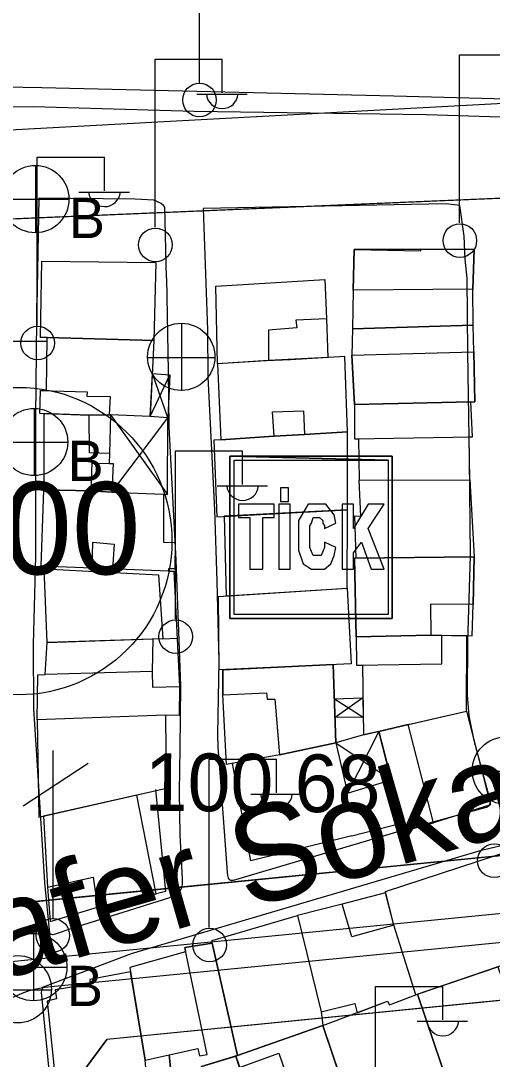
# Model space of a CAD drawing. Extents: x 417997 to 421451, y 4451742 to 4455216.
# Drawn here: x 419193.6 to 419242.7, y 4453532.7 to 4453640.7 of the extents above; entities that cross this region are included whole.
import ezdxf

# ---------------------------------------------------------------- set-up
doc = ezdxf.new("R2010")
doc.units = 0
for name, color, linetype in [('ADAKENARI', 7, 'Continuous'), ('B_Kapi', 7, 'Continuous'), ('B_Mesken', 7, 'Continuous'), ('B_Sundurma', 7, 'Continuous'), ('B_Teras', 7, 'Continuous'), ('Default', 7, 'Continuous'), ('KALDIRIM', 7, 'Continuous'), ('LJ_SEMBOL', 7, 'Continuous'), ('PL_AYA_PARK_DINLENME', 7, 'Continuous'), ('PL_TİCK', 7, 'Continuous'), ('S_Cad_Sok_Lambasi', 7, 'Continuous'), ('S_Cami_Mescid', 7, 'Continuous'), ('S_Elektrik_Diregi', 7, 'Continuous'), ('S_Rogar_Kapagi', 7, 'Continuous'), ('S_Rogar_Kapagi_Buski', 7, 'Continuous'), ('S_Telefon_Diregi', 7, 'Continuous'), ('Sinir_Duvar_tek_tarafa_ait', 7, 'Continuous'), ('Sinir_Tel_bir_taraf', 7, 'Continuous'), ('SM_TAKS', 7, 'Continuous'), ('TR_PARKALANI', 7, 'Continuous'), ('TR_TİCK', 7, 'Continuous'), ('Y_Cadde_Yol', 7, 'Continuous'), ('Y_Kot_Noktasi', 7, 'Continuous'), ('Yol_Sose', 7, 'Continuous')]:
    doc.layers.add(name, color=color, linetype=linetype)

# ---------------------------------------------------------------- blocks, each defined once
blk = doc.blocks.new('POINT_DISPLAY')
at = {"layer": 'Default'}
blk.add_line((0, 0), (0, 0), dxfattribs=at)

msp = doc.modelspace()

# ---------------------------------------------------------------- linework, layer by layer
at = {"layer": 'ADAKENARI'}
for p, q in [((419184.84, 4453619.74), (419327.19, 4453625.77)), ((419184.84, 4453619.74), (419327.19, 4453625.77)), ((419336.29, 4453563), (419170.94, 4453546.68)), ((419336.29, 4453563), (419170.94, 4453546.68)), ((419398.25, 4453554.05), (419202.53, 4453534.72)), ((419398.25, 4453554.05), (419202.53, 4453534.72)), ((419194.6, 4453523.95), (419202.53, 4453534.72)), ((419194.6, 4453523.95), (419202.53, 4453534.72))]:
    msp.add_line(p, q, dxfattribs=at)
at = {"layer": 'B_Kapi'}
msp.add_lwpolyline([(419228.07, 4453555.9), (419233.32, 4453557.24)], dxfattribs=at)
at = {"layer": 'B_Mesken'}
for points in [[(419240.67, 4453609.03), (419240.64, 4453612.77), (419240.78, 4453616.91), (419228.3, 4453616.91), (419228.2, 4453612.66), (419228.12, 4453608.66)], [(419196.33, 4453607.73), (419195.63, 4453607.73), (419195.77, 4453615.68), (419207.66, 4453615.53), (419207.45, 4453607.44)], [(419225.43, 4453609.7), (419225.56, 4453605.67), (419219.39, 4453605.34), (419214.05, 4453605.02), (419213.9, 4453613.1), (419225.25, 4453613.77)], [(419228.12, 4453608.66), (419228.07, 4453605.91), (419228.33, 4453600.78), (419240.44, 4453601.04), (419240.87, 4453601.05), (419240.75, 4453606.24), (419240.67, 4453609.03)], [(419207.07, 4453599.52), (419202.92, 4453599.7), (419202.78, 4453599.7), (419200.7, 4453599.65), (419195.58, 4453599.85), (419195.64, 4453602.24), (419196.27, 4453602.22), (419196.33, 4453607.73), (419207.45, 4453607.44)], [(419221.65, 4453605.43), (419219.12, 4453605.33), (419214.05, 4453605.02), (419214.42, 4453597.1), (419219.97, 4453597.48), (419223.13, 4453597.64), (419227.6, 4453597.92), (419227.31, 4453605.78)], [(419240.35, 4453592.93), (419240.28, 4453597.41), (419240.63, 4453597.42), (419240.44, 4453601.04), (419228.33, 4453600.78), (419228.33, 4453597.2), (419228.73, 4453597.2), (419228.83, 4453592.89)], [(419196.03, 4453591.9), (419196, 4453599.84), (419200.7, 4453599.65), (419202.78, 4453599.7), (419202.92, 4453599.7), (419202.82, 4453595.69), (419202.79, 4453594.63), (419203.21, 4453594.62), (419203.05, 4453591.65), (419200.92, 4453591.78), (419195.98, 4453591.9)], [(419214.42, 4453597.1), (419213.69, 4453597.06), (419213.98, 4453589.09), (419227.6, 4453589.82), (419227.6, 4453597.92), (419223.13, 4453597.64), (419219.97, 4453597.48)], [(419228.5, 4453584.8), (419228.37, 4453589.2), (419228.99, 4453589.14), (419228.83, 4453592.89), (419240.35, 4453592.93), (419240.8, 4453584.91)], [(419195.72, 4453583.94), (419195.98, 4453591.9), (419200.92, 4453591.78), (419203.05, 4453591.65), (419208.44, 4453591.44), (419208.44, 4453586.45), (419209.66, 4453586.42), (419209.61, 4453583.68), (419208.95, 4453583.68), (419208.95, 4453583.43)], [(419214.76, 4453589.14), (419214.97, 4453580.85), (419227.55, 4453581.66), (419227.6, 4453589.82)], [(419240.59, 4453576.69), (419240.7, 4453579.98), (419240.8, 4453584.91), (419228.34, 4453584.8), (419228.51, 4453576.61), (419236.28, 4453576.76)], [(419196.33, 4453576), (419196, 4453583.66), (419207.93, 4453583.04), (419208.38, 4453576.41)], [(419214.17, 4453580.79), (419227.55, 4453581.66), (419227.97, 4453573.8), (419214.24, 4453573.16)], [(419229.15, 4453573.66), (419229.28, 4453566.4), (419239.99, 4453568.88), (419240.02, 4453576.7), (419237.41, 4453576.74), (419236.28, 4453576.76), (419228.51, 4453576.61), (419228.54, 4453573.65)], [(419196.12, 4453572.67), (419196.33, 4453576), (419207.33, 4453576.38), (419207.25, 4453573.01), (419207.29, 4453571.38), (419210.12, 4453571.43), (419210.07, 4453568.42), (419208.67, 4453568.45), (419195.28, 4453567.97), (419195.37, 4453572.64)], [(419215.01, 4453563.31), (419214.63, 4453570.58), (419214.63, 4453573.18), (419226.12, 4453573.72), (419226.4, 4453565.58), (419220.51, 4453564.31)], [(419195.28, 4453567.97), (419195.47, 4453557.83), (419208.77, 4453560.84), (419208.67, 4453568.45)], [(419239.99, 4453568.88), (419242.49, 4453559.12), (419236.56, 4453557.25), (419233.53, 4453556.43), (419230.87, 4453566.76), (419233.93, 4453567.47)], [(419201.56, 4453548.47), (419207.69, 4453549.85), (419205.66, 4453560.14), (419195.94, 4453557.94), (419196.35, 4453550.54), (419196.64, 4453546.99)], [(419232.41, 4453546.61), (419231.55, 4453550.09), (419248.85, 4453555.75), (419249.06, 4453555.45), (419251.81, 4453545.22), (419248.63, 4453544.02), (419244.69, 4453542.75), (419243.26, 4453542.28), (419234.71, 4453539.34)], [(419231.57, 4453549.98), (419227.04, 4453548.8), (419222.4, 4453547.6), (419224.86, 4453537.58), (419228.36, 4453538.47), (419228.6, 4453537.5), (419231.78, 4453538.69), (419231.97, 4453538.31), (419234.71, 4453539.34), (419232.41, 4453546.61)], [(419213.5, 4453544.74), (419213.5, 4453545.01), (419222.4, 4453547.6), (419224.86, 4453537.58), (419225.04, 4453536.15), (419216.14, 4453533.04)], [(419204.93, 4453542.21), (419206.54, 4453532.55), (419209.04, 4453533.13), (419209.29, 4453530.71), (419212.47, 4453531.55), (419212.39, 4453531.9), (419216.14, 4453533.04), (419213.5, 4453544.74), (419210.65, 4453544.28), (419210.74, 4453543.84)], [(419238.22, 4453529.56), (419234.89, 4453539.41), (419243.26, 4453542.28), (419246.54, 4453532.66)], [(419205.01, 4453541.74), (419200.78, 4453540.94), (419200.8, 4453540.47), (419197.16, 4453539.86), (419197.29, 4453538.93), (419196.34, 4453538.7), (419197.57, 4453526.69), (419206.79, 4453529.84), (419206.54, 4453532.55)], [(419225.04, 4453536.15), (419231.78, 4453538.69), (419231.97, 4453538.31), (419234.89, 4453539.41), (419238.22, 4453529.56), (419238.46, 4453528.88), (419228.62, 4453525.55)], [(419228.5, 4453525.91), (419223.06, 4453524.01), (419223.03, 4453523.87), (419219.5, 4453522.6), (419218.29, 4453526.3), (419216.37, 4453531.8), (419215.96, 4453532.98), (419216.14, 4453533.04), (419225.04, 4453536.15)], [(419219.5, 4453522.6), (419209.49, 4453519.33), (419206.79, 4453529.84), (419209.29, 4453530.71), (419212.47, 4453531.55), (419212.39, 4453531.9), (419215.96, 4453532.98), (419216.87, 4453530.39), (419218.29, 4453526.3)]]:
    msp.add_lwpolyline(points, close=True, dxfattribs=at)
at = {"layer": 'B_Sundurma'}
for p, q in [((419207.07, 4453599.52), (419209.11, 4453603.85)), ((419208.91, 4453599.38), (419207.28, 4453604)), ((419202.92, 4453599.7), (419208.87, 4453591.41)), ((419203.05, 4453591.65), (419208.91, 4453599.38)), ((419226.24, 4453570.16), (419229.25, 4453568.26)), ((419229.21, 4453570.24), (419226.31, 4453568.22)), ((419230.87, 4453566.76), (419227.6, 4453560.35)), ((419226.4, 4453565.58), (419232.16, 4453561.74))]:
    msp.add_line(p, q, dxfattribs=at)
for points in [[(419208.91, 4453599.38), (419207.07, 4453599.52), (419207.28, 4453604), (419209.11, 4453603.85)], [(419207.07, 4453599.52), (419202.92, 4453599.7), (419202.82, 4453595.69), (419202.79, 4453594.63), (419202.79, 4453594.63), (419203.21, 4453594.62), (419203.05, 4453591.65), (419208.44, 4453591.44), (419208.87, 4453591.41), (419208.91, 4453599.38)], [(419226.24, 4453570.16), (419229.21, 4453570.24), (419229.25, 4453568.26), (419226.31, 4453568.22)], [(419230.87, 4453566.76), (419229.28, 4453566.4), (419226.4, 4453565.58), (419227.6, 4453560.35), (419232.16, 4453561.74)]]:
    msp.add_lwpolyline(points, close=True, dxfattribs=at)
at = {"layer": 'B_Teras'}
for points in [[(419228.2, 4453612.66), (419228.3, 4453616.91), (419235.22, 4453616.77), (419235.22, 4453616.77), (419235.22, 4453616.96), (419240.22, 4453616.94), (419240.78, 4453616.91), (419240.64, 4453612.77)], [(419214.05, 4453605.02), (419213.9, 4453613.1), (419225.25, 4453613.77), (419225.43, 4453609.7), (419222.23, 4453609.54), (419222.33, 4453608.75), (419219.37, 4453608.5), (419219.39, 4453605.34)], [(419228.07, 4453605.91), (419240.75, 4453606.24), (419240.87, 4453601.05), (419228.33, 4453600.78)], [(419202.78, 4453599.7), (419200.7, 4453599.65), (419195.58, 4453599.85), (419195.64, 4453602.24), (419200.49, 4453602.1), (419200.46, 4453601.64), (419202.88, 4453601.61)], [(419228.33, 4453600.78), (419228.33, 4453597.2), (419240.63, 4453597.42), (419240.44, 4453601.04)], [(419200.74, 4453595.73), (419200.7, 4453599.65), (419202.92, 4453599.7), (419202.82, 4453595.69)], [(419219.97, 4453597.48), (419219.78, 4453600.02), (419223.01, 4453600.12), (419223.13, 4453597.64)], [(419200.92, 4453591.78), (419201, 4453594.68), (419203.21, 4453594.62), (419203.05, 4453591.65)], [(419201.01, 4453583.73), (419201.08, 4453586.44), (419203.31, 4453586.24), (419203.14, 4453583.65)], [(419228.34, 4453584.8), (419240.8, 4453584.91), (419240.7, 4453579.98), (419236.25, 4453579.99), (419236.28, 4453576.76), (419228.51, 4453576.61)], [(419228.51, 4453576.61), (419228.54, 4453573.65), (419237.41, 4453573.79), (419237.41, 4453576.74), (419236.28, 4453576.76)], [(419207.33, 4453576.38), (419207.25, 4453573.01), (419196.12, 4453572.67), (419196.33, 4453576)], [(419214.63, 4453573.18), (419214.63, 4453570.58), (419219.18, 4453570.76), (419219.23, 4453570.11), (419220.02, 4453570.1), (419220.51, 4453564.31), (419226.4, 4453565.58), (419226.12, 4453573.72)], [(419230.87, 4453566.76), (419233.53, 4453556.43), (419236.56, 4453557.25), (419233.93, 4453567.47)], [(419195.94, 4453557.94), (419196.35, 4453550.54), (419201.12, 4453551.61), (419201.56, 4453548.47), (419207.69, 4453549.85), (419205.66, 4453560.14)], [(419234.71, 4453539.34), (419232.41, 4453546.61), (419228.04, 4453545.38), (419227.04, 4453548.8), (419222.4, 4453547.6), (419224.86, 4453537.58), (419228.36, 4453538.47), (419228.6, 4453537.5), (419231.78, 4453538.69), (419231.97, 4453538.31), (419234.89, 4453539.41)], [(419209.04, 4453533.13), (419212.03, 4453533.78), (419212.18, 4453533.02), (419213, 4453533.15), (419210.65, 4453544.28), (419213.5, 4453544.74), (419216.14, 4453533.04), (419212.39, 4453531.9), (419212.47, 4453531.55), (419209.29, 4453530.71)], [(419216.37, 4453531.8), (419220.45, 4453533.3), (419222.41, 4453527.66), (419218.33, 4453526.2)]]:
    msp.add_lwpolyline(points, close=True, dxfattribs=at)
at = {"layer": 'KALDIRIM'}
for p, q in [((419185.86, 4453629.01), (419323.39, 4453636.38)), ((419185.86, 4453629.01), (419323.39, 4453636.38)), ((419275.64, 4453550.98), (419171.53, 4453540.7)), ((419275.64, 4453550.98), (419171.53, 4453540.7)), ((419275.78, 4453547.98), (419196.41, 4453540.15)), ((419275.78, 4453547.98), (419196.41, 4453540.15))]:
    msp.add_line(p, q, dxfattribs=at)
msp.add_arc((419197.39, 4453530.2), 10, 95.6387, 191.7023, dxfattribs=at)
msp.add_arc((419197.39, 4453530.2), 10, 95.6387, 191.7023, dxfattribs=at)
at = {"layer": 'LJ_SEMBOL'}
for points in [[(419215.36, 4453595.4), (419231.82, 4453594.98), (419231.82, 4453578.94), (419215.79, 4453578.94), (419215.79, 4453594.98), (419231.82, 4453594.98), (419215.36, 4453595.4), (419215.36, 4453578.52), (419232.24, 4453578.52), (419232.24, 4453595.4), (419215.36, 4453595.4)], [(419215.36, 4453595.4), (419231.82, 4453594.98), (419231.82, 4453578.94), (419215.79, 4453578.94), (419215.79, 4453594.98), (419231.82, 4453594.98), (419215.36, 4453595.4), (419215.36, 4453578.52), (419232.24, 4453578.52), (419232.24, 4453595.4), (419215.36, 4453595.4)], [(419220.63, 4453592.09), (419220.63, 4453590.68), (419221.47, 4453590.68), (419221.47, 4453592.09), (419220.63, 4453592.09)], [(419220.63, 4453592.09), (419220.63, 4453590.68), (419221.47, 4453590.68), (419221.47, 4453592.09), (419220.63, 4453592.09)], [(419216.24, 4453590.4), (419216.24, 4453589), (419217.42, 4453589), (419217.42, 4453583.65), (419218.77, 4453583.65), (419218.77, 4453589), (419219.96, 4453589), (419219.96, 4453590.4), (419216.24, 4453590.4)], [(419216.24, 4453590.4), (419216.24, 4453589), (419217.42, 4453589), (419217.42, 4453583.65), (419218.77, 4453583.65), (419218.77, 4453589), (419219.96, 4453589), (419219.96, 4453590.4), (419216.24, 4453590.4)], [(419220.46, 4453590.4), (419220.46, 4453583.65), (419221.64, 4453583.65), (419221.64, 4453590.4), (419220.46, 4453590.4)], [(419220.46, 4453590.4), (419220.46, 4453583.65), (419221.64, 4453583.65), (419221.64, 4453590.4), (419220.46, 4453590.4)], [(419225.19, 4453586.46), (419225.19, 4453585.9), (419224.85, 4453585.06), (419224.51, 4453585.06), (419224.01, 4453585.06), (419223.67, 4453585.9), (419223.67, 4453587.31), (419223.67, 4453588.15), (419223.84, 4453588.43), (419224.01, 4453589), (419224.51, 4453589), (419224.68, 4453589), (419225.02, 4453588.71), (419225.02, 4453588.43), (419225.19, 4453588.15), (419225.19, 4453587.87), (419226.37, 4453588.43), (419226.2, 4453589.28), (419225.36, 4453590.4), (419224.68, 4453590.4), (419223.5, 4453590.4), (419222.49, 4453588.71), (419222.49, 4453587.31), (419222.49, 4453585.62), (419222.99, 4453584.21), (419223.84, 4453583.65), (419224.68, 4453583.65), (419225.19, 4453583.65), (419225.86, 4453584.21), (419226.2, 4453585.06), (419226.37, 4453585.9), (419225.19, 4453586.46)], [(419225.19, 4453586.46), (419225.19, 4453585.9), (419224.85, 4453585.06), (419224.51, 4453585.06), (419224.01, 4453585.06), (419223.67, 4453585.9), (419223.67, 4453587.31), (419223.67, 4453588.15), (419223.84, 4453588.43), (419224.01, 4453589), (419224.51, 4453589), (419224.68, 4453589), (419225.02, 4453588.71), (419225.02, 4453588.43), (419225.19, 4453588.15), (419225.19, 4453587.87), (419226.37, 4453588.43), (419226.2, 4453589.28), (419225.36, 4453590.4), (419224.68, 4453590.4), (419223.5, 4453590.4), (419222.49, 4453588.71), (419222.49, 4453587.31), (419222.49, 4453585.62), (419222.99, 4453584.21), (419223.84, 4453583.65), (419224.68, 4453583.65), (419225.19, 4453583.65), (419225.86, 4453584.21), (419226.2, 4453585.06), (419226.37, 4453585.9), (419225.19, 4453586.46)], [(419227.04, 4453590.4), (419227.04, 4453583.65), (419228.22, 4453583.65), (419228.22, 4453585.34), (419229.07, 4453586.46), (419230.08, 4453583.65), (419231.43, 4453583.65), (419229.74, 4453587.87), (419231.43, 4453590.4), (419229.74, 4453590.4), (419228.22, 4453587.87), (419228.22, 4453590.4), (419227.04, 4453590.4)], [(419227.04, 4453590.4), (419227.04, 4453583.65), (419228.22, 4453583.65), (419228.22, 4453585.34), (419229.07, 4453586.46), (419230.08, 4453583.65), (419231.43, 4453583.65), (419229.74, 4453587.87), (419231.43, 4453590.4), (419229.74, 4453590.4), (419228.22, 4453587.87), (419228.22, 4453590.4), (419227.04, 4453590.4)]]:
    msp.add_lwpolyline(points, dxfattribs=at)
at = {"layer": 'PL_AYA_PARK_DINLENME'}
msp.add_lwpolyline([(419391.61, 4453553.39), (419202.53, 4453534.72), (419194.6, 4453523.95), (419200.28, 4453496.52), (419202.37, 4453486.53), (419300, 4453506.67), (419368.97, 4453519.65), (419373.13, 4453497.59), (419398.11, 4453502.17), (419404.77, 4453503.86), (419391.61, 4453553.39)], dxfattribs=at)
msp.add_lwpolyline([(419391.61, 4453553.39), (419202.53, 4453534.72), (419194.6, 4453523.95), (419200.28, 4453496.52), (419202.37, 4453486.53), (419300, 4453506.67), (419368.97, 4453519.65), (419373.13, 4453497.59), (419398.11, 4453502.17), (419404.77, 4453503.86), (419391.61, 4453553.39)], dxfattribs=at)
at = {"layer": 'PL_TİCK'}
msp.add_lwpolyline([(419122.58, 4453540.83), (419170.94, 4453546.68), (419336.29, 4453563), (419344.8, 4453573.88), (419338.62, 4453616.3), (419327.19, 4453625.77), (419184.84, 4453619.74), (419123.4, 4453617.13)], dxfattribs=at)
msp.add_lwpolyline([(419122.58, 4453540.83), (419170.94, 4453546.68), (419336.29, 4453563), (419344.8, 4453573.88), (419338.62, 4453616.3), (419327.19, 4453625.77), (419184.84, 4453619.74), (419123.4, 4453617.13)], dxfattribs=at)
at = {"layer": 'S_Cad_Sok_Lambasi'}
msp.add_line((419212.19, 4453634.2), (419212.19, 4453648.88), dxfattribs=at)
msp.add_circle((419212.19, 4453632.45), 1.75, dxfattribs=at)
at = {"layer": 'S_Cami_Mescid'}
msp.add_line((419171.73, 4453607.35), (419196.23, 4453607.35), dxfattribs=at)
at = {"layer": 'S_Elektrik_Diregi'}
for p, q in [((419239.27, 4453619.66), (419239.27, 4453637.16)), ((419239.27, 4453637.16), (419246.27, 4453637.16)), ((419207.56, 4453619.21), (419207.56, 4453636.71)), ((419207.56, 4453636.71), (419214.56, 4453636.71)), ((419214.56, 4453633.21), (419214.56, 4453636.71)), ((419211.9, 4453633.07), (419217.15, 4453633.07)), ((419195.3, 4453609.01), (419195.3, 4453626.51)), ((419195.3, 4453626.51), (419202.3, 4453626.51)), ((419202.3, 4453623.01), (419202.3, 4453626.51)), ((419199.64, 4453622.87), (419204.89, 4453622.87)), ((419209.68, 4453578.45), (419209.68, 4453595.95)), ((419209.68, 4453595.95), (419216.68, 4453595.95)), ((419216.68, 4453592.45), (419216.68, 4453595.95)), ((419214.02, 4453592.31), (419219.27, 4453592.31)), ((419213.2, 4453546.37), (419213.2, 4453563.87)), ((419213.2, 4453563.87), (419220.2, 4453563.87)), ((419220.2, 4453560.37), (419220.2, 4453563.87)), ((419217.54, 4453560.23), (419222.79, 4453560.23)), ((419230.52, 4453522.74), (419230.52, 4453540.24)), ((419230.52, 4453540.24), (419237.52, 4453540.24)), ((419237.52, 4453536.74), (419237.52, 4453540.24)), ((419234.86, 4453536.6), (419240.11, 4453536.6))]:
    msp.add_line(p, q, dxfattribs=at)
for centre in [(419207.6, 4453617.38), (419239.3, 4453617.83), (419195.33, 4453607.17), (419209.72, 4453576.62), (419242.89, 4453553.3), (419213.24, 4453544.54)]:
    msp.add_circle(centre, 1.75, dxfattribs=at)
for centre in [(419214.56, 4453633.22), (419202.3, 4453623.02), (419216.68, 4453592.46), (419220.2, 4453560.39), (419237.53, 4453536.75)]:
    msp.add_arc(centre, 1.66, 184.8384, 355.1464, dxfattribs=at)
at = {"layer": 'S_Rogar_Kapagi'}
for p, q in [((419210.34, 4453602.2), (419210.34, 4453609.2)), ((419206.77, 4453605.67), (419213.77, 4453605.67)), ((419240.57, 4453562.62), (419247.57, 4453562.62)), ((419189.75, 4453539.88), (419196.75, 4453539.88))]:
    msp.add_line(p, q, dxfattribs=at)
for centre in [(419210.29, 4453605.73), (419244.09, 4453562.69), (419193.27, 4453539.94)]:
    msp.add_circle(centre, 3.5, dxfattribs=at)
at = {"layer": 'S_Rogar_Kapagi_Buski'}
for p, q in [((419195.1, 4453625.64), (419195.1, 4453618.64)), ((419191.6, 4453622.14), (419198.6, 4453622.14)), ((419194.97, 4453600.37), (419194.97, 4453593.37)), ((419191.47, 4453596.87), (419198.47, 4453596.87)), ((419194.89, 4453545.74), (419194.89, 4453538.74)), ((419191.39, 4453542.24), (419198.39, 4453542.24))]:
    msp.add_line(p, q, dxfattribs=at)
for centre in [(419195.1, 4453622.14), (419194.97, 4453596.87), (419194.89, 4453542.24)]:
    msp.add_circle(centre, 3.5, dxfattribs=at)
at = {"layer": 'S_Telefon_Diregi'}
for p, q in [((419196.95, 4453547.29), (419196.95, 4453564.79)), ((419193.84, 4453559.01), (419200.59, 4453563.46))]:
    msp.add_line(p, q, dxfattribs=at)
msp.add_circle((419196.92, 4453545.54), 1.75, dxfattribs=at)
at = {"layer": 'Sinir_Duvar_tek_tarafa_ait'}
for points in [[(419208.95, 4453583.43), (419209.51, 4453583.44), (419210.12, 4453571.43)], [(419208.38, 4453576.41), (419209.86, 4453576.45)]]:
    msp.add_lwpolyline(points, dxfattribs=at)
at = {"layer": 'Sinir_Tel_bir_taraf'}
for points in [[(419228.07, 4453555.9), (419217.53, 4453553.31), (419215.63, 4453563.42)], [(419207.62, 4453560.71), (419208.66, 4453550.11), (419207.03, 4453549.69)]]:
    msp.add_lwpolyline(points, dxfattribs=at)
at = {"layer": 'SM_TAKS'}
msp.add_circle((419193.33, 4453586.56), 15.99, dxfattribs=at)
msp.add_circle((419193.33, 4453586.56), 15.99, dxfattribs=at)
at = {"layer": 'TR_TİCK'}
for points in [[(419122.58, 4453540.83), (419170.94, 4453546.68), (419336.29, 4453563), (419344.8, 4453573.88), (419338.62, 4453616.3), (419327.19, 4453625.77), (419184.84, 4453619.74), (419123.4, 4453617.13)], [(419122.58, 4453540.83), (419170.94, 4453546.68), (419336.29, 4453563), (419344.8, 4453573.88), (419338.62, 4453616.3), (419327.19, 4453625.77), (419184.84, 4453619.74), (419123.4, 4453617.13)], [(419215.36, 4453595.4), (419232.24, 4453595.4), (419232.24, 4453578.52), (419215.36, 4453578.52), (419215.36, 4453595.4)], [(419215.36, 4453595.4), (419232.24, 4453595.4), (419232.24, 4453578.52), (419215.36, 4453578.52), (419215.36, 4453595.4)]]:
    msp.add_lwpolyline(points, dxfattribs=at)
msp.add_circle((419193.33, 4453586.56), 15.99, dxfattribs=at)
msp.add_circle((419193.33, 4453586.56), 15.99, dxfattribs=at)
at = {"layer": 'Yol_Sose'}
for points in [[(419275.65, 4453631.56), (419250.67, 4453632.38), (419232.44, 4453632.85), (419195.76, 4453633.72), (419176.32, 4453634.06), (419166.78, 4453633.8)], [(419166.88, 4453631.74), (419194.86, 4453631.79), (419211.65, 4453631.3), (419235.81, 4453630.95), (419255.57, 4453630.33), (419271.53, 4453629.87), (419275.19, 4453629.76), (419275.68, 4453629.98), (419276.02, 4453630.52), (419276.05, 4453630.9), (419275.97, 4453631.04), (419275.65, 4453631.56)], [(419208.77, 4453613.95), (419208.58, 4453621.31), (419208.45, 4453621.47), (419208.2, 4453621.69), (419207.44, 4453622.03), (419205.48, 4453622.12), (419195.45, 4453622.23), (419195.27, 4453610.97)], [(419240.07, 4453613.92), (419239.86, 4453615.91), (419239.75, 4453618.29), (419239.31, 4453621.48), (419237.86, 4453621.65), (419212.59, 4453621.15), (419213.01, 4453608.53)], [(419208.77, 4453613.95), (419208.93, 4453604.2), (419209, 4453598.46), (419209.72, 4453584.59)], [(419242.08, 4453558.88), (419242.35, 4453559.05), (419242.43, 4453559.2), (419242.48, 4453559.37), (419242.5, 4453559.48), (419240.78, 4453565.83), (419240.26, 4453568.39), (419240.08, 4453570.52), (419240.13, 4453576.07), (419240.4, 4453585.05), (419240.31, 4453595.12), (419240.12, 4453606.17), (419240.07, 4453613.92)], [(419196.1, 4453551.03), (419195.47, 4453561.05), (419194.95, 4453569.11), (419194.91, 4453575.84), (419195.15, 4453584.97), (419195.16, 4453599.48), (419195.29, 4453613.02)], [(419213.01, 4453608.53), (419213.06, 4453603.6), (419213.77, 4453589.8), (419213.98, 4453582.38), (419214.19, 4453574.04), (419214.07, 4453566.49), (419214.1, 4453565.13), (419214.33, 4453561.99)], [(419209.72, 4453584.59), (419210.2, 4453571.51), (419210.13, 4453564.94), (419210.09, 4453560.52), (419210.16, 4453555.99), (419210.4, 4453551.43), (419210.4, 4453550.97), (419210.34, 4453550.57), (419210.17, 4453550.19), (419210.04, 4453550.03), (419209.66, 4453549.77), (419208.98, 4453549.43), (419198.89, 4453546.25), (419197.05, 4453545.62), (419196.87, 4453545.59), (419196.68, 4453545.67), (419196.6, 4453545.78), (419196.1, 4453551.03)], [(419214.33, 4453561.99), (419215.07, 4453552.12), (419215.09, 4453551.78), (419215.16, 4453551.51), (419215.28, 4453551.37), (419215.43, 4453551.3), (419215.44, 4453551.3), (419215.74, 4453551.27), (419232.98, 4453556.4), (419242.08, 4453558.88)], [(419196.66, 4453530.13), (419195.75, 4453539.65), (419195.81, 4453539.9), (419195.88, 4453540.08), (419195.96, 4453540.19), (419205.11, 4453543.65), (419241.54, 4453554.41), (419260.23, 4453558.85), (419260.48, 4453558.92), (419260.65, 4453558.89), (419260.73, 4453558.85), (419260.74, 4453558.79), (419260.76, 4453558.71), (419261.43, 4453547.62), (419262.03, 4453538.18), (419262.02, 4453538.05), (419261.97, 4453537.91), (419261.88, 4453537.79), (419261.62, 4453537.56), (419247.69, 4453532.36)]]:
    msp.add_lwpolyline(points, dxfattribs=at)

# ---------------------------------------------------------------- block references
at = {"layer": 'TR_PARKALANI', "xscale": 0.1, "yscale": 0.10000000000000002}
msp.add_blockref('POINT_DISPLAY', (419235.21, 4453534.74), dxfattribs=at)
msp.add_blockref('POINT_DISPLAY', (419235.21, 4453534.74), dxfattribs=at)

# ---------------------------------------------------------------- texts
at = {"layer": 'S_Rogar_Kapagi_Buski'}
for p in [(419198.6, 4453618.08), (419198.47, 4453592.81), (419198.39, 4453538.18)]:
    msp.add_text('B', height=4.2, dxfattribs=at).set_placement(p)
at = {"layer": 'SM_TAKS'}
msp.add_text('400', height=9.593, dxfattribs=at).set_placement((419184.64, 4453583.11))
msp.add_text('400', height=9.593, dxfattribs=at).set_placement((419184.64, 4453583.11))
at = {"layer": 'Y_Cadde_Yol'}
msp.add_text('4. Zafer Sokak', height=10, rotation=16.0417, dxfattribs=at).set_placement((419169.23, 4453534.47))
at = {"layer": 'Y_Kot_Noktasi'}
msp.add_text('100.68 ', height=6, rotation=359.5357, dxfattribs=at).set_placement((419206.47, 4453558.51))

doc.saveas('drawing.dxf')
